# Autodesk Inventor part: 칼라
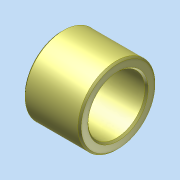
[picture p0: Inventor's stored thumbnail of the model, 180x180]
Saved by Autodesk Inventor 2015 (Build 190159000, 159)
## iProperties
Created: 2026-02
Part Number: 칼라
Material: 일반
Document SubType Name: Modeling
Designer: Administrator
Density: 1 g/cm^3
Appearance: 기본값
Author: Administrator
Author: jhkim
Creation Date: 2026-01-30
Sending System: Autodesk Inventor 2026
Preprocessor: ST-DEVELOPER v20.1
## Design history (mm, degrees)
node "칼라1"
node "솔리드1"
node "기준1"
